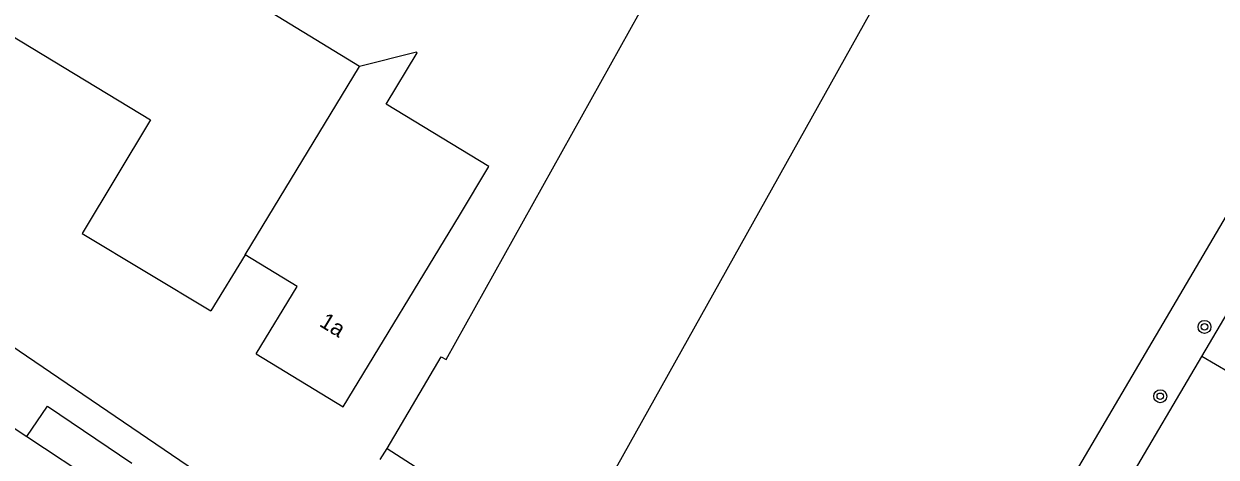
# Model space of a CAD drawing. Extents: x 136000 to 141014, y 402000 to 403500.
# Drawn here: x 137884.5 to 137958.3, y 402379.1 to 402405.9 of the extents above; entities that cross this region are included whole.
import ezdxf

# ---------------------------------------------------------------- set-up
doc = ezdxf.new("R2010")
doc.units = 0
for name, color, linetype in [('gg-afsc-hekwerk', 7, 'Continuous'), ('gg-anno-huisnummerreeks BGT', 7, 'Continuous'), ('gg-bbg-gedigitaliseerde bebouwing', 7, 'Continuous'), ('gg-bbg-hoofdgebouw', 7, 'Continuous'), ('gg-bbg-tussenscheiding', 7, 'Continuous'), ('gg-knt-verharding', 7, 'Continuous'), ('gg-knt-verharding nz', 7, 'Continuous'), ('gt-grn-weggrens', 7, 'Continuous'), ('gt-symb-boom', 7, 'Continuous')]:
    doc.layers.add(name, color=color, linetype=linetype)

# ---------------------------------------------------------------- blocks, each defined once
blk = doc.blocks.new('gt0-BOOM')
at = {"layer": 'gt-symb-boom'}
for radius in [0.4, 0.2]:
    blk.add_circle((0, 0), radius, dxfattribs=at)

msp = doc.modelspace()

# ---------------------------------------------------------------- linework, layer by layer
at = {"layer": 'gg-afsc-hekwerk'}
msp.add_line((137963.102, 402401.12), (137941.79, 402364.894), dxfattribs=at)
at = {"layer": 'gg-bbg-gedigitaliseerde bebouwing'}
for p, q in [((137905.322, 402403.277), (137879.698, 402418.96)), ((137904.31, 402382.23), (137911.494, 402394.073))]:
    msp.add_line(p, q, dxfattribs=at)
for points in [[(137907.02, 402379.66), (137910.367, 402385.332), (137910.677, 402385.166), (137925.629, 402411.982), (137922.918, 402413.46), (137926.302, 402419.33)], [(137911.494, 402394.073), (137913.325, 402397.092), (137906.958, 402400.954), (137908.89, 402404.139), (137908.831, 402404.174), (137905.322, 402403.277)]]:
    msp.add_lwpolyline(points, dxfattribs=at)
at = {"layer": 'gg-bbg-hoofdgebouw'}
for p, q in [((137898.228, 402391.628), (137896.12, 402388.16)), ((137898.92, 402385.5), (137904.31, 402382.23)), ((137907.02, 402379.66), (137910.512, 402377.418))]:
    msp.add_line(p, q, dxfattribs=at)
for points in [[(137936.55, 402368.224), (137936.69, 402368.44), (137921.2, 402378.45), (137955.16, 402439.23)], [(137870.933, 402424.156), (137870.74, 402423.84), (137870.88, 402423.75), (137863.27, 402411.14), (137871.26, 402406.35), (137874.74, 402412.15), (137877.65, 402410.38), (137877, 402409.3), (137892.38, 402399.99), (137888.16, 402392.95), (137896.12, 402388.16)], [(137898.92, 402385.5), (137901.451, 402389.672), (137898.228, 402391.628)]]:
    msp.add_lwpolyline(points, dxfattribs=at)
at = {"layer": 'gg-bbg-tussenscheiding'}
msp.add_line((137898.228, 402391.628), (137905.322, 402403.277), dxfattribs=at)
at = {"layer": 'gg-knt-verharding'}
for p, q in [((137944.313, 402363.101), (137957.433, 402385.336)), ((137879.154, 402384.043), (137884.717, 402380.387)), ((137884.717, 402380.387), (137886.004, 402382.261)), ((137886.004, 402382.261), (137891.226, 402378.75)), ((137906.582, 402378.973), (137907.02, 402379.66))]:
    msp.add_line(p, q, dxfattribs=at)
for points in [[(137857.248, 402404.049), (137900.191, 402374.842), (137902.334, 402373.476)], [(137957.433, 402385.336), (137964.575, 402397.441), (137963.3, 402401.003)]]:
    msp.add_lwpolyline(points, dxfattribs=at)
at = {"layer": 'gg-knt-verharding nz'}
msp.add_line((137884.717, 402380.387), (137893.726, 402374.478), dxfattribs=at)
at = {"layer": 'gt-grn-weggrens'}
msp.add_line((137962.169, 402382.559), (137957.433, 402385.336), dxfattribs=at)

# ---------------------------------------------------------------- block references
at = {"layer": 'gt-symb-boom'}
for p in [(137957.605, 402387.176), (137954.87, 402382.885)]:
    msp.add_blockref('gt0-BOOM', p, dxfattribs=at)

# ---------------------------------------------------------------- texts
at = {"layer": 'gg-anno-huisnummerreeks BGT'}
msp.add_text('1a', height=1, rotation=328.7, dxfattribs=at).set_placement((137902.766, 402387.262))

doc.saveas('drawing.dxf')
